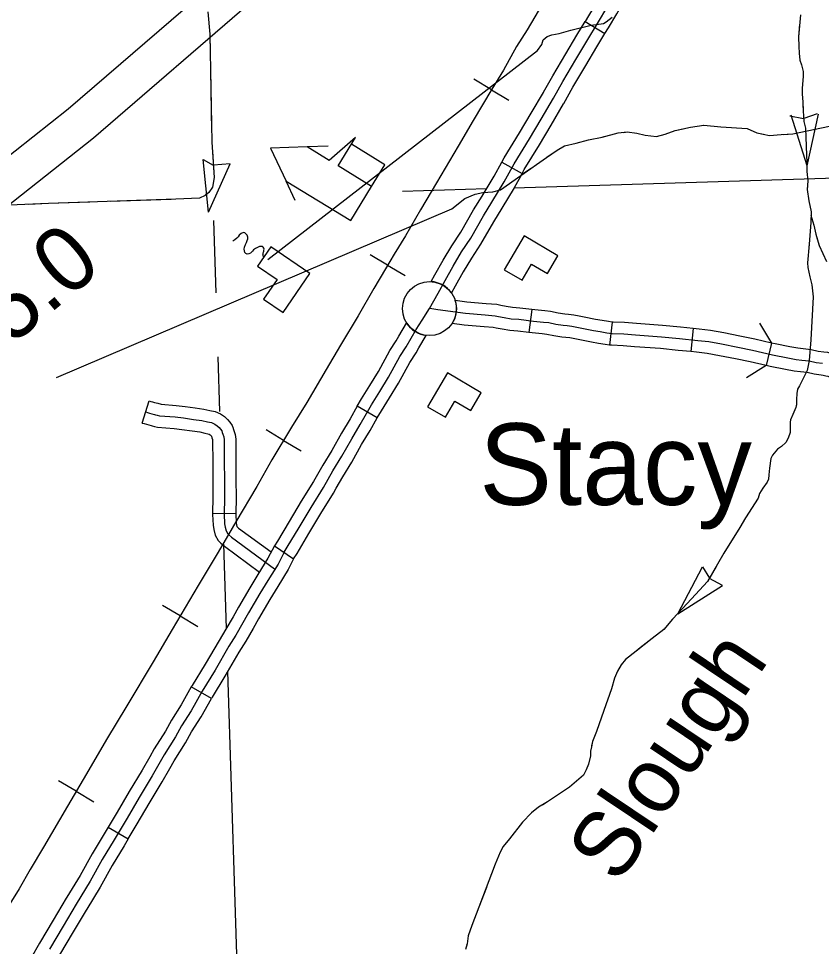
# Model space of a CAD drawing. Extents: x -117616 to 64730, y 54117 to 789866.
# Drawn here: x 63172.5 to 63276.5, y 54758.9 to 54879.2 of the extents above; entities that cross this region are included whole.
import ezdxf

# ---------------------------------------------------------------- set-up
doc = ezdxf.new("R2010")
doc.units = 0
for name, color, linetype in [('15', 7, 'Continuous'), ('24', 7, 'Continuous'), ('31', 7, 'Continuous'), ('32', 7, 'Continuous'), ('38', 7, 'Continuous'), ('40', 7, 'Continuous'), ('43', 7, 'Continuous'), ('45', 7, 'Continuous'), ('48', 7, 'Continuous'), ('5', 7, 'Continuous'), ('57', 7, 'Continuous'), ('58', 7, 'Continuous')]:
    doc.layers.add(name, color=color, linetype=linetype)

msp = doc.modelspace()

# ---------------------------------------------------------------- linework, layer by layer
at = {"layer": '15'}
for p, q in [((63178.97, 54867.45), (63201.02, 54886.5)), ((63204.32, 54882.74), (63182.24, 54863.66)), ((63164.16, 54855.76), (63178.97, 54867.45)), ((63182.24, 54863.66), (63167.32, 54851.88))]:
    msp.add_line(p, q, dxfattribs=at)
at = {"layer": '24'}
msp.add_circle((63225.76, 54841.58), 3.5, dxfattribs=at)
at = {"layer": '31'}
for p, q in [((63245.9, 54878.75), (63248.47, 54877.2)), ((63235.12, 54860.53), (63237.74, 54859.07)), ((63219, 54827.43), (63216.39, 54828.92)), ((63205.68, 54810.86), (63208.16, 54809.18)), ((63208.16, 54809.18), (63208.16, 54809.18)), ((63197.51, 54791.08), (63194.9, 54792.56)), ((63192.12, 54782), (63192.12, 54782)), ((63184.15, 54774.42), (63186.73, 54772.89))]:
    msp.add_line(p, q, dxfattribs=at)
for points in [[(63251.29, 54887.84), (63250.35, 54886.3), (63248.95, 54883.93), (63247.45, 54881.29), (63246.36, 54879.52), (63245.9, 54878.75)], [(63248.47, 54877.2), (63248.93, 54877.96), (63250.03, 54879.76), (63251.55, 54882.42), (63252.93, 54884.76), (63253.85, 54886.28)], [(63225.76, 54841.58), (63226.87, 54843.56), (63227.77, 54845.2), (63228.83, 54847.09), (63229.92, 54848.92), (63231.09, 54850.7), (63232.76, 54853.59), (63233.84, 54855.35), (63235.42, 54857.99), (63236.73, 54860.33), (63238.71, 54863.58), (63240.21, 54866.11), (63241.83, 54868.84), (63243.04, 54871), (63244.71, 54873.84), (63246.15, 54876.24), (63247.65, 54878.74), (63248.74, 54880.52)], [(63240.54, 54869.61), (63241.75, 54871.75), (63243.42, 54874.6), (63244.86, 54877.01), (63245.9, 54878.75)], [(63243.15, 54868.13), (63244.34, 54870.25), (63246, 54873.08), (63247.44, 54875.47), (63248.47, 54877.2)], [(63235.12, 54860.53), (63235.43, 54861.09), (63237.42, 54864.35), (63238.92, 54866.88), (63240.53, 54869.59), (63240.54, 54869.61)], [(63237.74, 54859.07), (63238.02, 54859.58), (63239.99, 54862.81), (63241.5, 54865.35), (63243.13, 54868.09), (63243.15, 54868.13)], [(63229.82, 54851.49), (63231.47, 54854.35), (63232.56, 54856.13), (63234.12, 54858.74), (63235.12, 54860.53)], [(63237.74, 54859.07), (63236.71, 54857.24), (63235.12, 54854.58), (63234.05, 54852.82), (63232.37, 54849.91)], [(63225.99, 54845.08), (63226.46, 54845.93), (63227.53, 54847.84), (63228.65, 54849.72), (63229.82, 54851.49)], [(63232.37, 54849.91), (63231.2, 54848.12), (63230.13, 54846.34), (63229.08, 54844.48), (63228.61, 54843.61)], [(63206.92, 54810.02), (63207.34, 54810.65), (63208.86, 54813.22), (63210.42, 54815.83), (63212.02, 54818.42), (63213.23, 54820.55), (63214.4, 54822.45), (63215.68, 54824.7), (63216.77, 54826.56), (63218.23, 54829.12), (63219.31, 54830.82), (63220.43, 54832.68), (63221.93, 54835.36), (63222.74, 54836.64), (63224.04, 54838.86), (63224.82, 54840.08), (63225.76, 54841.58)], [(63221.8, 54838.01), (63222.8, 54839.71)], [(63216.39, 54828.92), (63216.95, 54829.89), (63218.03, 54831.61), (63219.14, 54833.43), (63220.64, 54836.13), (63221.46, 54837.42), (63221.8, 54838.01)], [(63224.39, 54836.49), (63225.34, 54838.11)], [(63219, 54827.43), (63219.52, 54828.34), (63220.59, 54830.03), (63221.73, 54831.92), (63223.22, 54834.6), (63224.02, 54835.86), (63224.39, 54836.49)], [(63216.39, 54828.92), (63215.47, 54827.31), (63214.38, 54825.45), (63213.11, 54823.21), (63211.93, 54821.31), (63211.08, 54819.79)], [(63213.69, 54818.31), (63214.52, 54819.78), (63215.69, 54821.69), (63216.97, 54823.95), (63218.07, 54825.8), (63219, 54827.43)], [(63211.08, 54819.79), (63210.73, 54819.19), (63209.14, 54816.61), (63207.57, 54813.99), (63206.08, 54811.45), (63205.68, 54810.86)], [(63208.16, 54809.18), (63208.61, 54809.85), (63210.15, 54812.46), (63211.7, 54815.05), (63213.32, 54817.66), (63213.69, 54818.31)], [(63205.68, 54810.86), (63204.83, 54809.23), (63203.54, 54807.15), (63202.51, 54805.42), (63201.03, 54802.91), (63200.31, 54801.64)], [(63206.92, 54810.02), (63206.14, 54808.49), (63204.83, 54806.37), (63203.8, 54804.65), (63202.33, 54802.16), (63200.68, 54799.28), (63199.79, 54797.83), (63197.98, 54794.75), (63196.31, 54792), (63194.88, 54789.48), (63193.63, 54787.52), (63192.87, 54786.09), (63191.4, 54783.77), (63189.84, 54781.05), (63188.17, 54778.23), (63186.59, 54775.58), (63184.91, 54772.77), (63183.38, 54770.2), (63181.79, 54767.39), (63180.01, 54764.42), (63178.32, 54761.59), (63176.55, 54758.6)], [(63208.16, 54809.18), (63207.45, 54807.76), (63206.11, 54805.59), (63205.09, 54803.89), (63203.63, 54801.4), (63202.91, 54800.15)], [(63200.31, 54801.64), (63199.39, 54800.04), (63198.5, 54798.6), (63196.69, 54795.52), (63195.01, 54792.76), (63194.9, 54792.56)], [(63202.91, 54800.15), (63201.97, 54798.51), (63201.07, 54797.05), (63199.27, 54793.98), (63197.6, 54791.24), (63197.51, 54791.08)], [(63194.9, 54792.56), (63193.59, 54790.25), (63192.34, 54788.27), (63191.58, 54786.84), (63190.12, 54784.54), (63189.52, 54783.49)], [(63192.12, 54782), (63192.69, 54782.99), (63194.17, 54785.33), (63194.93, 54786.76), (63196.17, 54788.71), (63197.51, 54791.08)], [(63189.52, 54783.49), (63188.55, 54781.8), (63186.88, 54779), (63185.3, 54776.35), (63184.15, 54774.42)], [(63186.73, 54772.89), (63187.88, 54774.81), (63189.46, 54777.47), (63191.14, 54780.29), (63192.12, 54782)], [(63184.15, 54774.42), (63183.63, 54773.54), (63182.08, 54770.95), (63180.5, 54768.14), (63178.8, 54765.33)], [(63186.73, 54772.89), (63186.2, 54772), (63184.67, 54769.45), (63183.09, 54766.63), (63181.38, 54763.78)], [(63178.8, 54765.33), (63178.72, 54765.19), (63177.03, 54762.35), (63175.26, 54759.35), (63174.17, 54757.49), (63173.42, 54756.24)], [(63181.38, 54763.78), (63181.3, 54763.65), (63179.6, 54760.82), (63177.85, 54757.84), (63176.75, 54755.96), (63176, 54754.7)]]:
    msp.add_lwpolyline(points, dxfattribs=at)
for start, end in [(35.4118, 86.1679), (212.2873, 263.0754)]:
    msp.add_arc((63225.76, 54841.58), 3.5, start, end, dxfattribs=at)
at = {"layer": '32'}
for p, q in [((63239, 54841.46), (63238.63, 54838.49)), ((63249.42, 54839.83), (63249.05, 54836.85)), ((63259.9, 54838.99), (63259.62, 54836)), ((63270.05, 54837.12), (63269.37, 54834.2))]:
    msp.add_line(p, q, dxfattribs=at)
for points in [[(63239, 54841.46), (63237.46, 54841.65), (63236.51, 54841.71), (63235.68, 54841.86), (63234.98, 54841.97), (63234.48, 54842.09), (63233.08, 54842.2), (63230.59, 54842.43), (63229.1, 54842.63)], [(63276.64, 54834.45), (63275.83, 54834.55), (63274.94, 54834.76), (63273.98, 54834.86), (63273.23, 54834.95), (63272.15, 54835.15), (63270.19, 54835.55), (63267.59, 54836.15), (63265.67, 54836.53), (63263.59, 54836.95), (63261.95, 54837.26), (63260.51, 54837.42), (63258.12, 54837.65), (63255.81, 54837.88), (63252.44, 54838.14), (63250.92, 54838.27), (63249.43, 54838.32), (63248.72, 54838.4), (63247.88, 54838.55), (63247, 54838.7), (63245.49, 54838.99), (63244.84, 54839.11), (63244.19, 54839.25), (63243.57, 54839.33), (63243.09, 54839.38), (63242.14, 54839.53), (63241.2, 54839.72), (63240.52, 54839.79), (63239.21, 54839.92), (63237.32, 54840.16), (63236.33, 54840.22), (63235.43, 54840.38), (63234.69, 54840.5), (63234.25, 54840.6), (63232.95, 54840.71), (63230.42, 54840.94), (63226.85, 54841.42), (63225.78, 54841.58)], [(63249.42, 54839.83), (63248.94, 54839.89), (63248.13, 54840.03), (63247.26, 54840.18), (63245.77, 54840.47), (63245.13, 54840.59), (63244.45, 54840.72), (63243.75, 54840.82), (63243.27, 54840.87), (63242.41, 54841), (63241.43, 54841.2), (63240.68, 54841.28), (63239.38, 54841.41), (63239, 54841.46)], [(63238.63, 54838.49), (63237.18, 54838.67), (63236.15, 54838.73), (63235.18, 54838.9), (63234.41, 54839.03), (63234.02, 54839.12), (63232.83, 54839.21), (63230.25, 54839.45), (63228.68, 54839.66)], [(63259.9, 54838.99), (63258.26, 54839.15), (63255.94, 54839.38), (63252.56, 54839.63), (63251.01, 54839.77), (63249.54, 54839.81), (63249.42, 54839.83)], [(63249.05, 54836.85), (63248.5, 54836.92), (63247.63, 54837.07), (63246.73, 54837.22), (63245.21, 54837.52), (63244.56, 54837.64), (63243.94, 54837.77), (63243.4, 54837.84), (63242.9, 54837.89), (63241.88, 54838.05), (63240.97, 54838.23), (63240.36, 54838.3), (63239.04, 54838.43), (63238.63, 54838.49)], [(63270.05, 54837.12), (63267.9, 54837.62), (63265.96, 54838), (63263.88, 54838.42), (63262.17, 54838.74), (63260.67, 54838.92), (63259.9, 54838.99)], [(63280.57, 54834.6), (63280.33, 54834.74), (63279.68, 54835.1), (63278.95, 54835.36), (63278.27, 54835.64), (63277.82, 54835.73), (63277.33, 54835.88), (63276.82, 54835.94), (63276.1, 54836.03), (63275.19, 54836.24), (63274.14, 54836.35), (63273.45, 54836.43), (63272.44, 54836.63), (63270.51, 54837.02), (63270.05, 54837.12)], [(63259.62, 54836), (63257.97, 54836.16), (63255.68, 54836.39), (63252.32, 54836.64), (63250.83, 54836.77), (63249.31, 54836.82), (63249.05, 54836.85)], [(63269.37, 54834.2), (63267.27, 54834.69), (63265.38, 54835.06), (63263.3, 54835.47), (63261.72, 54835.77), (63260.35, 54835.93), (63259.62, 54836)], [(63278.99, 54832.05), (63278.84, 54832.14), (63278.44, 54832.35), (63277.87, 54832.56), (63277.39, 54832.76), (63277.08, 54832.82), (63276.74, 54832.93), (63276.47, 54832.96), (63275.56, 54833.07), (63274.68, 54833.28), (63273.81, 54833.37), (63273, 54833.46), (63271.86, 54833.68), (63269.87, 54834.08), (63269.37, 54834.2)]]:
    msp.add_lwpolyline(points, dxfattribs=at)
msp.add_arc((63225.76, 54841.58), 3.5, 326.6598, 17.4152, dxfattribs=at)
at = {"layer": '38'}
for points in [[(63268.48, 54839.67), (63270.06, 54837.12)], [(63269.37, 54834.2), (63266.82, 54832.62)]]:
    msp.add_lwpolyline(points, dxfattribs=at)
at = {"layer": '40'}
for p, q in [((63233.77, 54869.93), (63231.5, 54871.28)), ((63233.77, 54869.93), (63236.04, 54868.58)), ((63220.34, 54847.2), (63218.07, 54848.56)), ((63220.34, 54847.2), (63222.6, 54845.85)), ((63206.86, 54824.5), (63204.6, 54825.87)), ((63206.86, 54824.5), (63209.12, 54823.14)), ((63193.46, 54801.76), (63191.19, 54803.1)), ((63193.46, 54801.76), (63195.74, 54800.41)), ((63180, 54779.05), (63177.73, 54780.39)), ((63180, 54779.05), (63182.28, 54777.7))]:
    msp.add_line(p, q, dxfattribs=at)
for points in [[(63240.83, 54881.82), (63238.42, 54877.68), (63237.04, 54875.51), (63235.34, 54872.45), (63233.81, 54870.01), (63231.41, 54865.96), (63229.47, 54862.61), (63226.68, 54857.88), (63224.6, 54854.38), (63222.63, 54851), (63221.19, 54848.62), (63220.05, 54846.72), (63218.55, 54844.16), (63216.53, 54840.66), (63214.24, 54836.82), (63212.36, 54833.7), (63209.86, 54829.41), (63207.9, 54826.21), (63205.34, 54821.98), (63203.4, 54818.51), (63200.67, 54813.96), (63199.71, 54812.32), (63198.24, 54809.82), (63195.8, 54805.7), (63192.43, 54800), (63189.96, 54795.8), (63186.58, 54790.13), (63183.94, 54785.76), (63181.33, 54781.29), (63178.86, 54777.12), (63175.75, 54771.8), (63174.05, 54768.92), (63172.61, 54766.4), (63170.32, 54762.72)], [(63240.83, 54881.82), (63238.42, 54877.68), (63237.04, 54875.51), (63235.34, 54872.45), (63233.81, 54870.01), (63231.41, 54865.96), (63229.47, 54862.61), (63226.68, 54857.88), (63224.6, 54854.38), (63222.63, 54851), (63221.19, 54848.62), (63220.05, 54846.72), (63218.55, 54844.16), (63216.53, 54840.66), (63214.24, 54836.82), (63212.36, 54833.7), (63209.86, 54829.41), (63207.9, 54826.21), (63205.34, 54821.98), (63203.4, 54818.51), (63200.67, 54813.96), (63199.71, 54812.32)], [(63199.71, 54812.32), (63198.24, 54809.82), (63195.8, 54805.7), (63192.43, 54800), (63189.96, 54795.8), (63186.58, 54790.13), (63183.94, 54785.76), (63181.33, 54781.29), (63178.86, 54777.12), (63175.75, 54771.8), (63174.05, 54768.92), (63172.61, 54766.4), (63170.32, 54762.72), (63168.3, 54759.26), (63166.65, 54756.38), (63165.13, 54753.88), (63163.01, 54750.33), (63161.69, 54748.09), (63160.72, 54746.39), (63159.37, 54744.13), (63158.2, 54742.13), (63156.88, 54739.99)]]:
    msp.add_lwpolyline(points, dxfattribs=at)
at = {"layer": '43'}
for p, q in [((63272.41, 54866.54), (63274.2, 54866.21)), ((63274.66, 54860.08), (63272.6, 54866.63)), ((63275.95, 54866.81), (63274.23, 54866.21)), ((63274.66, 54860.08), (63276.15, 54866.78)), ((63196.44, 54860.88), (63197.75, 54860.15)), ((63197.15, 54854.05), (63196.44, 54860.88)), ((63197.15, 54854.05), (63199.95, 54860.32)), ((63199.95, 54860.32), (63197.78, 54860.15)), ((63257.91, 54802.05), (63261.12, 54808.12)), ((63261.12, 54808.12), (63262, 54806.64)), ((63263.72, 54805.7), (63262.02, 54806.62)), ((63257.91, 54802.05), (63263.72, 54805.7))]:
    msp.add_line(p, q, dxfattribs=at)
for points in [[(63197.05, 54880.04), (63197.31, 54877.12), (63197.56, 54863.13), (63197.87, 54858.57), (63197.66, 54857.29), (63197.2, 54856.62), (63196.69, 54856.21), (63195.98, 54855.9), (63192.9, 54855.75), (63176.41, 54855.19), (63169.25, 54854.88)], [(63204.83, 54847.95), (63239.74, 54875), (63240.32, 54875.79), (63240.47, 54876.41), (63241.01, 54876.81), (63241.62, 54877.06), (63242.56, 54877.21), (63244.05, 54877.64), (63246.69, 54878.29), (63248.28, 54878.51), (63248.64, 54878.73), (63249.4, 54879.31)], [(63273.81, 54879.64), (63273.53, 54876.8), (63273.58, 54875.53), (63273.64, 54874.65), (63273.74, 54873.77), (63273.93, 54873.15), (63274.16, 54872.31), (63274.16, 54871.69), (63274.01, 54870.1), (63274.03, 54869.37), (63274.1, 54868.35), (63274.14, 54867.2), (63274.24, 54865.83), (63274.45, 54864.95), (63274.6, 54861.47), (63274.62, 54860.53), (63274.62, 54859.32), (63274.74, 54858.11), (63274.68, 54857), (63274.89, 54855.54), (63275.18, 54854.1), (63275.16, 54852.73), (63274.91, 54849.91), (63274.7, 54847.49), (63274.74, 54846.89), (63275.01, 54845.68), (63275.28, 54844.65), (63275.45, 54843.11), (63275.16, 54837.52), (63274.93, 54834.85), (63274.68, 54833.54), (63273.68, 54831.58), (63273.43, 54831.14), (63273.35, 54830.58), (63273.3, 54829.8), (63273.3, 54829.2), (63273.2, 54828.78), (63272.8, 54827.86), (63272.51, 54827.18), (63272.45, 54826.86), (63272.45, 54826.42), (63272.49, 54825.97), (63272.49, 54825.51), (63272.2, 54824.78), (63271.89, 54824.25), (63271.35, 54823.71), (63270.82, 54823.38), (63270.2, 54822.61), (63269.95, 54822.15), (63269.78, 54820.92), (63269.7, 54820.04), (63269.66, 54819.5), (63269.47, 54819.1), (63268.91, 54818.31), (63268.51, 54817.64), (63268.34, 54817.02), (63266.7, 54814.47), (63265.97, 54813.2), (63263.88, 54809.88), (63261.78, 54806.23), (63260.22, 54804.54), (63258.57, 54802.77), (63257.22, 54801.35), (63256.11, 54800.02), (63254.59, 54798.85), (63252.53, 54797.18), (63251.15, 54796.1), (63250.57, 54795.43), (63250.11, 54794.59), (63249.71, 54793.68), (63249.34, 54792.34), (63248.34, 54789.5), (63247.38, 54786.79), (63246.86, 54785.5), (63246.73, 54784.81), (63246.63, 54784.23), (63246.59, 54783.64), (63246.36, 54782.56), (63246.04, 54781.81)], [(63273.69, 54878.44), (63273.53, 54876.8), (63273.58, 54875.53), (63273.64, 54874.65), (63273.74, 54873.77), (63273.93, 54873.15), (63274.16, 54872.31), (63274.16, 54871.69), (63274.06, 54870.6)], [(63197.31, 54876.69), (63197.34, 54875.1)], [(63177.47, 54832.67), (63228.67, 54854.5), (63230.33, 54855.84), (63231.67, 54856.38), (63232.65, 54856.6), (63233.95, 54856.71), (63234.96, 54856.96), (63237.57, 54858.84), (63240.9, 54861.16), (63242.31, 54862.1), (63243.25, 54862.68), (63244.74, 54863.01), (63246.36, 54863.44), (63248.14, 54863.8), (63250.2, 54864.35), (63251.36, 54864.46), (63252.59, 54864.31), (63253.67, 54864.06), (63255.16, 54863.88), (63256.28, 54864.17), (63257.58, 54864.64), (63259.57, 54865.07), (63261.27, 54865.33), (63263.48, 54865.14), (63266.92, 54864.89), (63268.15, 54864.35), (63269.78, 54863.99), (63271.3, 54864.13), (63272.82, 54864.2), (63316.32, 54873.32)], [(63197.39, 54872.46), (63197.54, 54864.55)], [(63274.11, 54867.97), (63274.14, 54867.2), (63274.24, 54865.83), (63274.45, 54864.95), (63274.6, 54861.47), (63274.62, 54860.53), (63274.62, 54860.08)], [(63250.91, 54864.41), (63251.36, 54864.46), (63252.59, 54864.31), (63253.67, 54864.06), (63255.16, 54863.88), (63256.28, 54864.17), (63257.58, 54864.64), (63258.63, 54864.87)], [(63261.23, 54865.32), (63261.27, 54865.33), (63263.48, 54865.14), (63266.92, 54864.89), (63268.15, 54864.35), (63269, 54864.16)], [(63240.98, 54861.22), (63242.31, 54862.1), (63243.25, 54862.68), (63244.74, 54863.01), (63246.36, 54863.44), (63248.14, 54863.8), (63248.34, 54863.86)], [(63271.62, 54864.15), (63272.82, 54864.2), (63274.47, 54864.55)], [(63197.64, 54861.91), (63197.87, 54858.57), (63197.66, 54857.29), (63197.2, 54856.62), (63196.69, 54856.21), (63195.98, 54855.9), (63194.95, 54855.85)], [(63237.64, 54858.89), (63238.82, 54859.71)], [(63274.71, 54857.45), (63274.68, 54857), (63274.89, 54855.54), (63275.18, 54854.1), (63275.17, 54853.53)], [(63181.76, 54855.37), (63176.41, 54855.19), (63173.84, 54855.08)], [(63188.35, 54855.59), (63184.4, 54855.46)], [(63192.31, 54855.73), (63188.35, 54855.59)], [(63275.17, 54853.53), (63275.16, 54852.73), (63274.91, 54849.91), (63274.88, 54849.58)], [(63275.14, 54853.67), (63275.55, 54852.37), (63275.78, 54851.24), (63276.21, 54849.77), (63277.16, 54847.69)], [(63275.14, 54853.67), (63275.55, 54852.37), (63275.78, 54851.24), (63276.18, 54849.86)], [(63274.74, 54846.95), (63274.74, 54846.89), (63275.01, 54845.68), (63275.28, 54844.65), (63275.45, 54843.11), (63275.24, 54839.11)], [(63274.55, 54833.29), (63273.68, 54831.58), (63273.43, 54831.14), (63273.35, 54830.58), (63273.3, 54829.8), (63273.3, 54829.2), (63273.23, 54828.91)], [(63262.89, 54808.16), (63261.78, 54806.23), (63260.22, 54804.54), (63258.57, 54802.77), (63257.9, 54802.06)], [(63256.16, 54800.08), (63256.11, 54800.02), (63254.59, 54798.85), (63253.06, 54797.61)], [(63253.06, 54797.61), (63252.53, 54797.18), (63251.15, 54796.1), (63250.57, 54795.43), (63250.26, 54794.87)], [(63249.35, 54792.4), (63249.34, 54792.34), (63248.34, 54789.5), (63247.38, 54786.79), (63246.86, 54785.5), (63246.75, 54784.93)], [(63246.04, 54781.81), (63245.69, 54781.14), (63243.9, 54779.6), (63241.06, 54777.66), (63239.87, 54776.99), (63238.96, 54776.24), (63237.79, 54775.05), (63236.14, 54772.9), (63235.31, 54771.9), (63234.89, 54771.17), (63234.27, 54769.6), (63232.14, 54764.04), (63231.25, 54761.64), (63230.75, 54760.32), (63230.62, 54759.3), (63230.43, 54758.55)], [(63246.27, 54782.35), (63246.04, 54781.81), (63245.69, 54781.14), (63243.9, 54779.6), (63241.06, 54777.66), (63240.38, 54777.27)], [(63238.35, 54775.62), (63237.79, 54775.05), (63236.14, 54772.9), (63235.31, 54771.9), (63234.89, 54771.17), (63234.27, 54769.6), (63234.06, 54769.05)], [(63233.12, 54766.59), (63232.14, 54764.04), (63231.25, 54761.64), (63230.75, 54760.32), (63230.62, 54759.3), (63230.57, 54759.11)]]:
    msp.add_lwpolyline(points, dxfattribs=at)
at = {"layer": '45'}
for p, q in [((63188.56, 54826.75), (63189.45, 54829.62)), ((63197.66, 54815.08), (63200.66, 54815.02))]:
    msp.add_line(p, q, dxfattribs=at)
for points in [[(63189.45, 54829.62), (63189.68, 54829.55), (63189.9, 54829.48), (63190.15, 54829.42), (63190.56, 54829.31), (63190.69, 54829.27), (63190.86, 54829.23), (63191.01, 54829.19), (63192.96, 54829.03), (63194.1, 54828.9), (63195.4, 54828.7), (63196.52, 54828.57), (63197.32, 54828.39), (63197.98, 54828.24), (63198.67, 54827.94), (63199.2, 54827.58), (63199.59, 54827.23), (63199.89, 54826.86), (63200.18, 54826.45), (63200.32, 54826.09)], [(63189.01, 54828.19), (63189.24, 54828.11), (63189.5, 54828.03), (63189.79, 54827.96), (63190.14, 54827.87), (63190.27, 54827.83), (63190.5, 54827.77), (63190.77, 54827.7), (63192.81, 54827.54), (63193.9, 54827.41), (63195.2, 54827.21), (63196.26, 54827.09), (63196.99, 54826.92), (63197.51, 54826.8), (63197.94, 54826.62), (63198.27, 54826.4), (63198.5, 54826.19), (63198.7, 54825.94), (63198.85, 54825.74), (63198.92, 54825.54), (63199, 54825.31), (63199.11, 54824.95), (63199.17, 54824.56), (63199.18, 54821.68), (63199.19, 54819.45), (63199.21, 54817.08), (63199.16, 54814.94), (63199.22, 54813.68), (63199.28, 54813.26), (63199.42, 54812.79), (63199.62, 54812.41), (63199.71, 54812.32)], [(63188.56, 54826.75), (63188.79, 54826.68), (63189.1, 54826.59), (63189.43, 54826.51), (63189.71, 54826.43), (63189.85, 54826.39), (63190.14, 54826.32), (63190.52, 54826.22), (63192.67, 54826.05), (63193.7, 54825.93), (63195, 54825.73), (63196.01, 54825.61), (63196.66, 54825.46), (63197.05, 54825.37), (63197.21, 54825.3), (63197.34, 54825.21), (63197.42, 54825.14), (63197.51, 54825.03), (63197.5, 54825.06)], [(63197.5, 54825.06), (63197.51, 54825.04), (63197.58, 54824.84), (63197.64, 54824.62), (63197.67, 54824.45), (63197.68, 54821.67), (63197.69, 54819.44), (63197.71, 54817.09), (63197.66, 54815.08)], [(63200.32, 54826.09), (63200.33, 54826.04), (63200.43, 54825.77), (63200.58, 54825.28), (63200.67, 54824.67), (63200.68, 54821.69), (63200.69, 54819.46), (63200.71, 54817.07), (63200.66, 54815.02)], [(63197.66, 54815.08), (63197.66, 54814.92), (63197.72, 54813.53), (63197.82, 54812.94), (63198.02, 54812.22), (63198.39, 54811.54), (63198.74, 54811.17)], [(63200.66, 54815.02), (63200.66, 54814.95), (63200.71, 54813.83), (63200.75, 54813.58), (63200.82, 54813.34)], [(63200.82, 54813.34), (63201.04, 54813.15), (63205.26, 54810.05)], [(63199.71, 54812.32), (63200.12, 54811.97), (63205.7, 54807.87)], [(63198.74, 54811.17), (63199.19, 54810.79), (63203.73, 54807.45)]]:
    msp.add_lwpolyline(points, dxfattribs=at)
at = {"layer": '5'}
for points in [[(63302.14, 54859.22), (63236.69, 54857.19)], [(63233.13, 54857.08), (63222.24, 54856.75)], [(63197.77, 54852.97), (63198.07, 54843.61)], [(63198.33, 54835.31), (63198.55, 54828.24)], [(63199.09, 54811.08), (63199.43, 54800.12)], [(63199.61, 54794.55), (63201.01, 54749.72)]]:
    msp.add_lwpolyline(points, dxfattribs=at)
at = {"layer": '57'}
for p, q in [((63212.65, 54862.6), (63209.91, 54862.52)), ((63208.37, 54855.6), (63207.19, 54858.08))]:
    msp.add_line(p, q, dxfattribs=at)
for points in [[(63215.55, 54852.97), (63218.26, 54857.41), (63213.94, 54860.06), (63216.19, 54863.75), (63212.76, 54860.77), (63209.91, 54862.52), (63205.16, 54862.37), (63207.19, 54858.08)], [(63206.8, 54841.07), (63210.27, 54846.11), (63205.23, 54849.59), (63203.49, 54847.07), (63206.01, 54845.33), (63204.28, 54842.81)]]:
    msp.add_lwpolyline(points, close=True, dxfattribs=at)
for points in [[(63218.26, 54857.41), (63219.98, 54860.22), (63215.65, 54862.86)], [(63204.29, 54848.26), (63204.27, 54848.3), (63204.24, 54848.34), (63204.22, 54848.4), (63204.21, 54848.46), (63204.2, 54848.5), (63204.2, 54848.55), (63204.19, 54848.6), (63204.2, 54848.65), (63204.21, 54848.75), (63204.23, 54848.82), (63204.25, 54848.89), (63204.29, 54849.01), (63204.32, 54849.13), (63204.34, 54849.28), (63204.31, 54849.41), (63204.23, 54849.52), (63204.12, 54849.61), (63203.97, 54849.64), (63203.76, 54849.63), (63203.47, 54849.51), (63203.24, 54849.38), (63202.98, 54849.17), (63202.82, 54849.02), (63202.7, 54848.9), (63202.57, 54848.77), (63202.36, 54848.65), (63202.15, 54848.62), (63201.96, 54848.71), (63201.84, 54848.86), (63201.78, 54849.05), (63201.76, 54849.28), (63201.8, 54849.52), (63201.92, 54849.87), (63202.04, 54850.16), (63202.15, 54850.42), (63202.22, 54850.62), (63202.22, 54850.85), (63202.14, 54851.11), (63201.99, 54851.27), (63201.83, 54851.38), (63201.67, 54851.42), (63201.38, 54851.31), (63201.11, 54851.07), (63200.97, 54850.89), (63200.81, 54850.71), (63200.53, 54850.47), (63200.28, 54850.32)]]:
    msp.add_lwpolyline(points, dxfattribs=at)
at = {"layer": '58'}
for points in [[(63238.01, 54851.01), (63235.43, 54846.62), (63237.74, 54845.27), (63238.96, 54847.34), (63241.03, 54846.13), (63242.39, 54848.43)], [(63228.07, 54833.24), (63225.5, 54828.86), (63227.81, 54827.5), (63229.03, 54829.58), (63231.1, 54828.36), (63232.45, 54830.67)]]:
    msp.add_lwpolyline(points, close=True, dxfattribs=at)

# ---------------------------------------------------------------- texts
at = {"layer": '24'}
msp.add_text('Stacy', height=10.56, dxfattribs=at).set_placement((63232.2, 54816.15))
at = {"layer": '43'}
msp.add_text('Slough', height=8.448, rotation=56.1355, dxfattribs=at).set_placement((63250.19, 54766.82))
at = {"layer": '48'}
msp.add_text('5.0', height=8.448, rotation=39.8303, dxfattribs=at).set_placement((63171.59, 54836.7))

doc.saveas('drawing.dxf')
